Omron CX-Programmer project 新工程 (CX-Programmer 4.01)

# PLC 新PLC1: CS1G-H CPU45

## Program 新程序1 (cyclic task 0)

### Section 段1

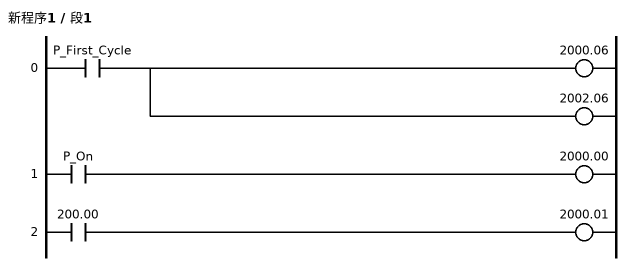
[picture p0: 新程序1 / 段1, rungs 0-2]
; rung 0
LD P_First_Cycle
OUT 2000.06
OUT 2002.06
; rung 1
LD P_On
OUT 2000.00
; rung 2
LD 200.00
OUT 2000.01

### Section END
; rung 0
END(001)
